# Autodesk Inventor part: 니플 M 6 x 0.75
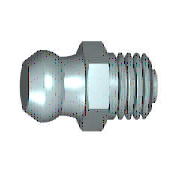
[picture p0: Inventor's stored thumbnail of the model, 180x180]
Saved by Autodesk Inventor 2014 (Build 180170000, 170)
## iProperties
IsCustomPart: 1
Created: 2012-02
Part Number: 니플 M 6 x 0.75
Material: 강철, 연강
Description: 윤활 니플, 원추 유형 A
Document SubType Name: Modeling
Standard: JIS B 1575
Designer: mduedu
Standards Organization: JIS
Language: ko-KR
Size Designation: MT 6 x 0.75
Categories: <MemberInstance><Categories><Category DisplayName="기타 부품" InternalName="5aa15e00-363f-49f2-933f-16f664388e3f" Mnemonic="OTHER"><Category DisplayName="그리스 부속품" I
Density: 1 g/cm^3
Appearance: Steel
Author: mduedu
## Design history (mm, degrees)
sketch "스케치1"
  geometry: L1 (-8.8, 0)-(-8.8, 2.4); L2 (-8.8, 2.4)-(-7.335, 3.202); L3 (-8.8, 0)-(4.7, 0); L4 (4.7, 0)-(4.7, 1.5); L5 (4.7, 1.5)-(4, 1.5); L6 (4, 1.5)-(4, 3); L7 (4, 3)-(0, 3); L8 (-11.5, 0)-(7.4, 0) reference; L9 (0, -1.733)-(0, 10.398) reference; L10 (-3, 3.5)-(0, 3.5); L11 (0, 3.5)-(0, 3); A1 r 3.3 centre (-6.535, 0) between (-4.789, 2.8) and (-7.335, 3.202); A2 r 6 centre (-6.053, 8.665) between (-4.789, 2.8) and (-3, 3.5)
  constraints: 18 end point, 5 perpendicular, 4 point on circle, 2 centre point, 2 parallel, 2 point on line, 1 collinear, 1 vertical
  dimensions: "d0" = 13.5 distance between parallel lines of L1 L4 (= GL); "d1" = 5.6 diameter of A1.start L3 (= KGB2); "d2" = 0.7 distance between parallel lines of L4 L6 (= PHH); "d3" = 3 diameter of L5 L3 (= 0.5 x NND); "d4" = 6 diameter of L7 L3 (= NND); "d5" = 6.6 dimension on A1 L3 (= KR); "d6" = 4.8 diameter of L1.end L3 (= KGB1); "d7" = 6 radius of A2 (= RBN); "d11" = 7 diameter of L10.start L3 (= SW); "d14" = 3 distance of L10.start L10.end (= KOH); "d15" = 4 distance between parallel lines of L6 L11 (= NLG); "d61" = 7.33505 distance from line of L9 L2.end (computed from KGB1, KR, PHH, GL, NLG, VERS); "d62" = 6.53505 distance from line of L9 A1.centre (computed from NLG, GL, PHH, KR, KGB1)
revolve "본체" sketch "스케치1" stored, may be unused: angle "d25" = 90 deg
sketch "스케치2"
  geometry: L1 (2.021, 3.5)-(4.041, 0); L2 (4.041, 0)-(2.021, -3.5); L3 (2.021, -3.5)-(-2.021, -3.5); L4 (-2.021, -3.5)-(-4.041, 0); L5 (-4.041, 0)-(-2.021, 3.5); L6 (-2.021, 3.5)-(2.021, 3.5); C1 r 3.5 at (0, 0) reference; 1 further point
  constraints: 12 end point, 1 coincident, 1 horizontal, 1 tangent, 11 other
extrude "머리" join sketch "스케치2" distance "d17" = 3 (= KOH); taper "d18" = 0 deg
sketch "스케치3"
  geometry: L1 (2.687, 4.041)-(3, 4.041); L2 (3, 4.041)-(3, 3.5); L3 (3, 3.5)-(2.687, 4.041); L4 (0.313, 4.041)-(0, 4.041); L5 (0, 4.041)-(0, 3.5); L6 (0, 3.5)-(0.313, 4.041); L7 (3.6, 0)-(-0.6, 0) reference; L8 (0, 4.041)-(0, 2.021) reference; L9 (0, 4.041)-(3, 4.041) reference; L10 (3, 3.031)-(3, 4.041) reference
  constraints: 12 end point, 4 collinear, 3 perpendicular, 1 horizontal
  dimensions: "d19" = 3.5 distance from line of L5.end L7 (= 0.5 x SW); "d20" = 3.5 distance from line of L2.end L7 (= 0.5 x SW); "d21" = 30 deg angle of L6 L5; "d22" = 30 deg angle of L2 L3
revolve "모따기1" sketch "스케치3" stored, may be unused: angle "d56" = 90 deg
body "Solid1"
fillet "모깎기1" dims "d8" = 0.2 (= RR)
feature "스레드1" dims "d9" = 3.53991 (= NLG - GAL), "d10" = 0
chamfer "모따기2" distance "d23" = 0.46009 (= -0.5 x GD1 + 0.5 x NND); stored, may be unused: angle "d24" = 45 deg, second distance "d59" = 0.46009 (= -0.5 x GD1 + 0.5 x NND)
other parameters: "NLG" = 4 [user parameter; used in 4 equation terms], "GL" = 13.5 [user parameter; used in 3 equation terms], "NND" = 6 [user parameter; used in 4 equation terms], "KGB1" = 4.8 [user parameter; used in 3 equation terms], "KGB2" = 5.6 [user parameter; used in 1 equation term], "VERS" = 0.8 [user parameter; used in 1 equation term], "KR" = 6.6 [user parameter; used in 3 equation terms], "RBN" = 6 [user parameter; used in 1 equation term], "SW" = 7 [user parameter; used in 3 equation terms], "KOH" = 3 [user parameter; used in 2 equation terms], "GAL" = 0.46009 (= 0.61345 x PTC) [user parameter; used in 1 equation term], "FAWI" = 45 deg [user parameter], "PHH" = 0.7 [user parameter; used in 3 equation terms], "GD1" = 5.07983 (= THREADDIA - 1.2269 x PTC) [user parameter; used in 2 equation terms], "RR" = 0.2 [user parameter; used in 1 equation term], "d12" = 0, "d13" = 0, "GUL" = 0.46009 (= 0.61345 x PTC) [user parameter], "TPU" = 13.33333 (computed from PTC) [user parameter], "DULO" = 1.5 [user parameter], "PTC" = 0.75 [user parameter; used in 4 equation terms], "GEL" = 4 [user parameter], "THREADDIA" = 6 [user parameter; used in 1 equation term], "TOA" = 30 deg [user parameter]
